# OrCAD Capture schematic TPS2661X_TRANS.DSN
size D; title: TPS2661x : 50V, Universal : 4-20mA, ±20mA Current Loop; rev: 1.0; note: Datasheet: SLVSFE3- MAY2020     EVM: PSIL116; note: Protector with Input/Output Miswiring Protection
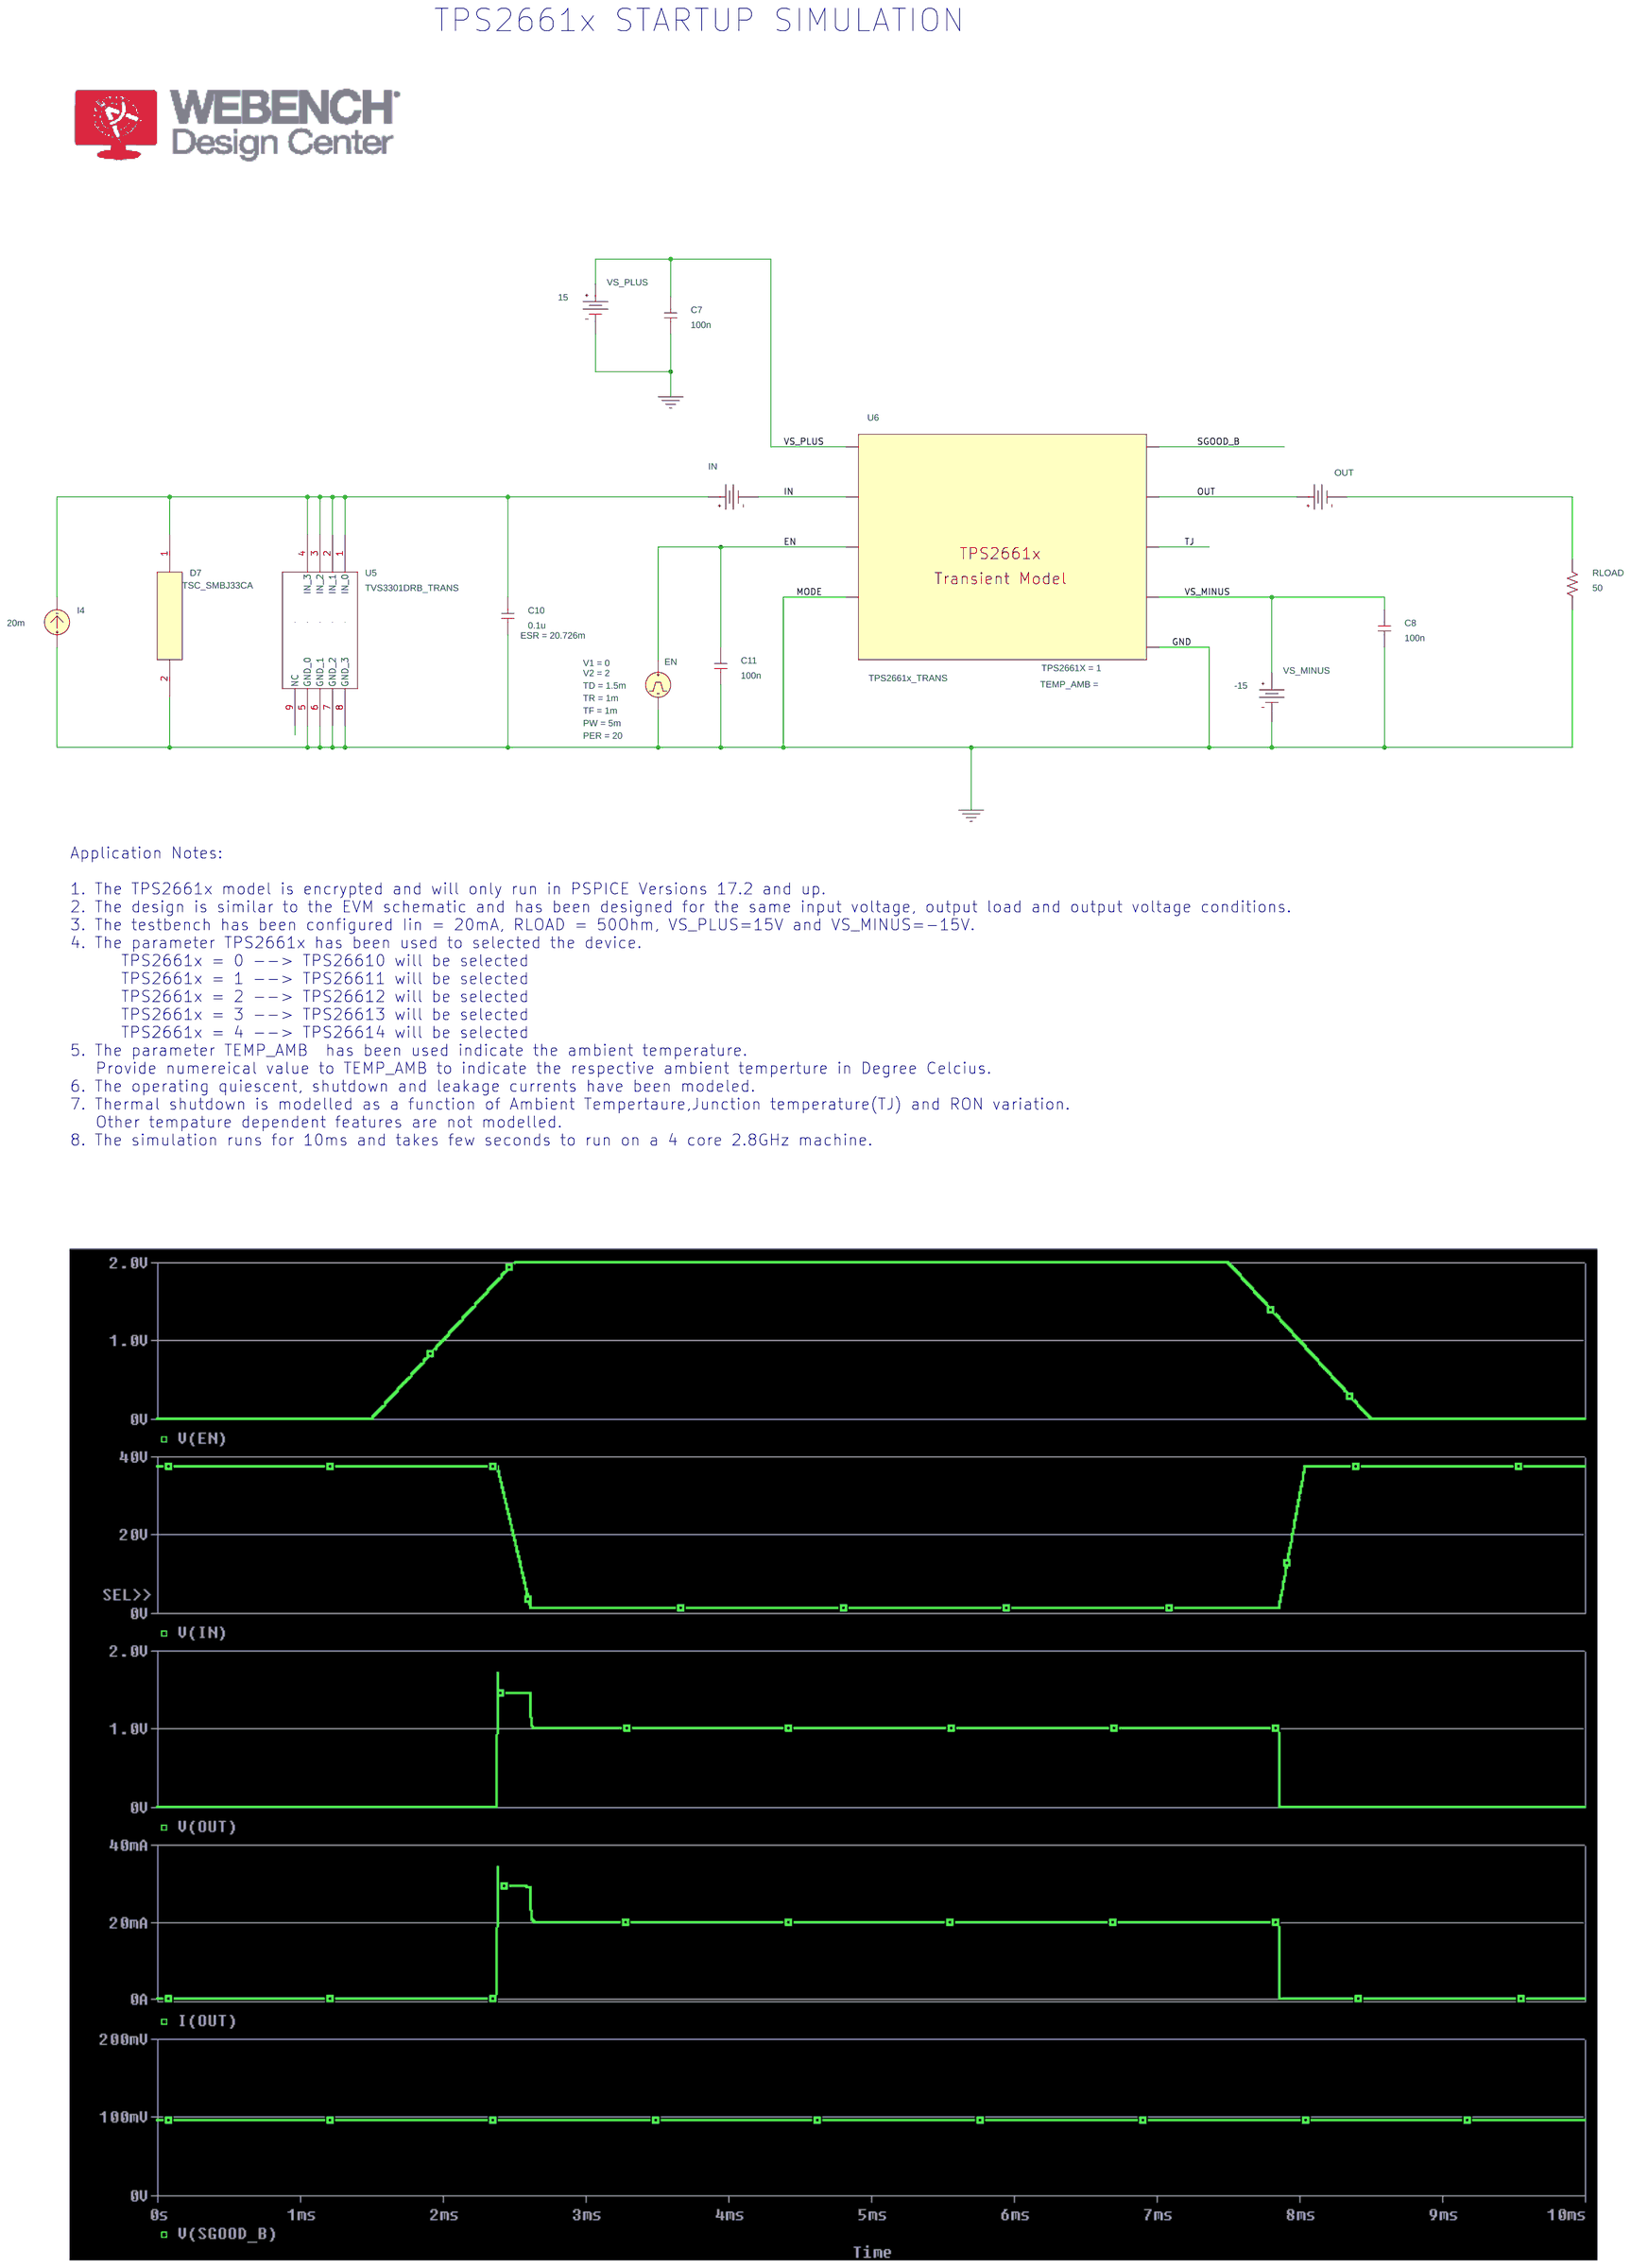
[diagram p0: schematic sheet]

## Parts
C7  100n  [RAD/CK05]
C8  100n  [RAD/CK05]
C10  0.1u  [RAD/CK05]
C11  100n  [RAD/CK05]
D7  TSC_SMBJ33CA
EN  VPULSE
I4  IDC
IN  VDC
OUT  VDC
RLOAD  50  [AX/RC05]
U5  TVS3301DRB_TRANS  [DRB0008A]
U6  TPS2661x_TRANS
VS_MINUS  VDC
VS_PLUS  VDC

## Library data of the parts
C7 C8 C11 = C
C10 = C: AppProp: InductiveSlave:;SRF:;PrevCap:0.1u;PrevESL:; ESR: 20.726m
D7 = TSC_SMBJ33CA
EN = VPULSE: PER: 20; PW: 5m; TD: 1.5m; TF: 1m; TR: 1m; V1: 0; V2: 2
I4 = IDC: DC: 20m
IN OUT = VDC
RLOAD = R
U5 = TVS3301DRB_TRANS
U6 = TPS2661x_TRANS: TPS2661X: 1
VS_MINUS = VDC: DC: -15
VS_PLUS = VDC: DC: 15

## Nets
0: C7.1 C8.1 C10.2 C11.1 D7.2 EN.2(-) I4.1(+) RLOAD.1 U5.5(GND_0) U5.6(GND_1) U5.7(GND_2) U5.8(GND_3) U6.GND U6.MODE VS_MINUS.1(-) VS_PLUS.1(-)
EN: C11.2 EN.1(+) U6.EN
IN: IN.1(-) U6.IN
OUT: OUT.0(+) U6.OUT
SGOOD_B: U6.SGOOD_B
TJ: U6.TJ
VS_MINUS: C8.2 U6.VS_MINUS VS_MINUS.0(+)
VS_PLUS: C7.2 U6.VS_PLUS VS_PLUS.0(+)
N16595435: C10.1 D7.1 I4.2(-) IN.0(+) U5.1(IN_0) U5.2(IN_1) U5.3(IN_2) U5.4(IN_3)
N16603724: OUT.1(-) RLOAD.2

Not connected (* = marked no-connect by the designer): U5 9(NC)

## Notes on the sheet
- TPS2661x STARTUP SIMULATION
- Application Notes:
  1. The TPS2661x model is encrypted and will only run in PSPICE Versions 17.2 and up.
  2. The design is similar to the EVM schematic and has been designed for the same input voltage, output load and output voltage conditions.
  3. The testbench has been configured Iin = 20mA, RLOAD = 50Ohm, VS_PLUS=15V and VS_MINUS=-15V.
  4. The parameter TPS2661x has been used to selected the device.
        TPS2661x = 0 --> TPS26610 will be selected
        TPS2661x = 1 --> TPS26611 will be selected
        TPS2661x = 2 --> TPS26612 will be selected
        TPS2661x = 3 --> TPS26613 will be selected
        TPS2661x = 4 --> TPS26614 will be selected
  5. The parameter TEMP_AMB  has been used indicate the ambient temperature.
     Provide numereical value to TEMP_AMB to indicate the respective ambient temperture in Degree Celcius.
  6. The operating quiescent, shutdown and leakage currents have been modeled.
  7. Thermal shutdown is modelled as a function of Ambient Tempertaure,Junction temperature(TJ) and RON variation.
     Other tempature dependent features are not modelled.
  8. The simulation runs for 10ms and takes few seconds to run on a 4 core 2.8GHz machine.
